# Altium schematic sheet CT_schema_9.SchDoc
size 274 x 160 mm
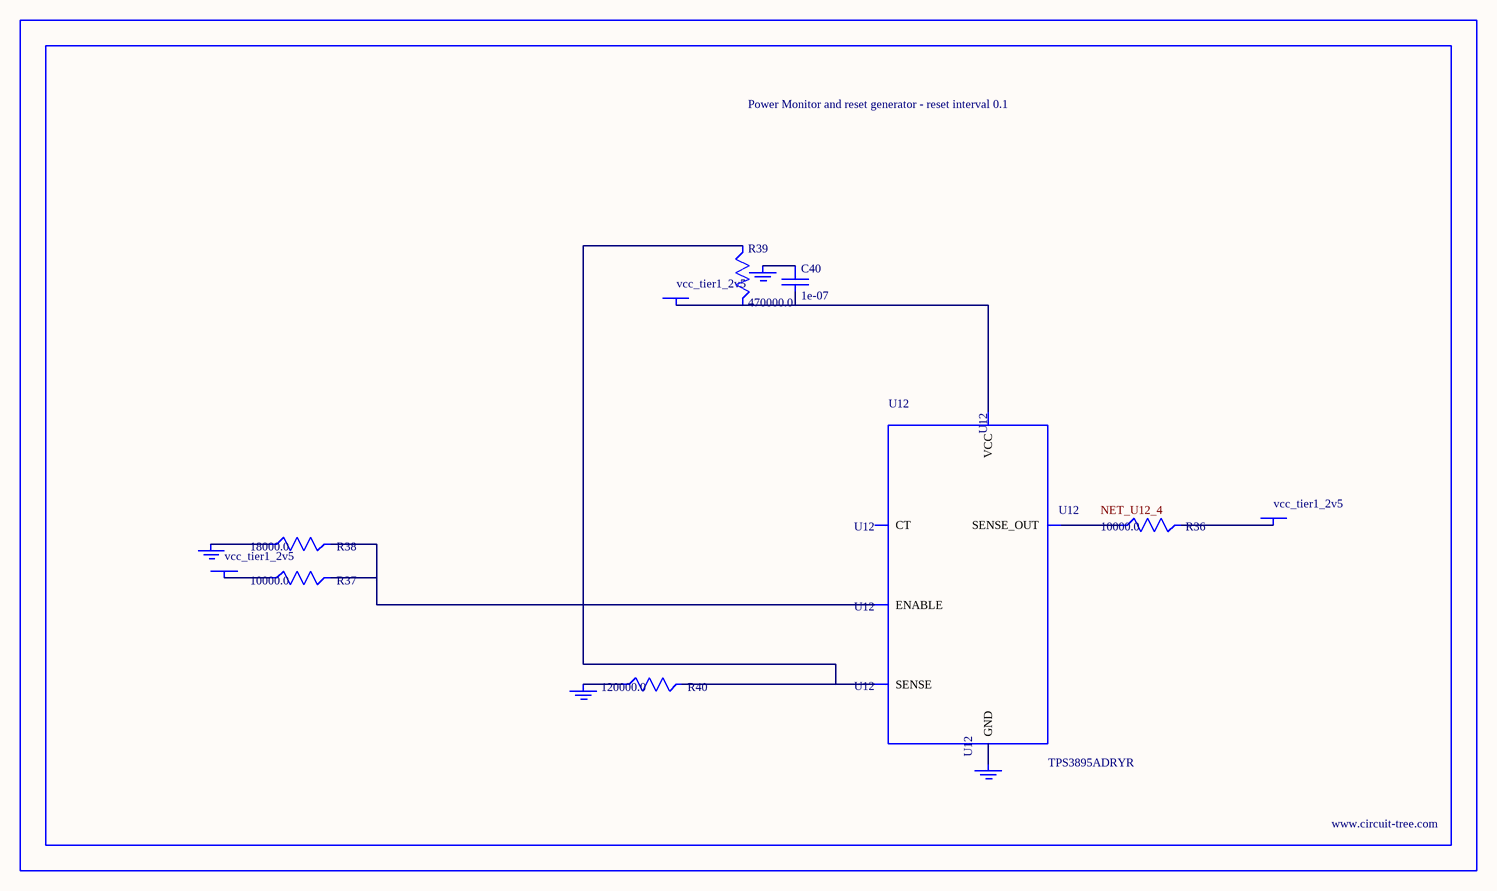
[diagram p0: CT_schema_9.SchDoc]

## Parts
BORDER8  (no value)
C40  1e-07  [C0402]
GND_INSTANCE_8_0  (no value)
GND_INSTANCE_8_1  (no value)
GND_INSTANCE_8_2  (no value)
GND_INSTANCE_8_3  (no value)
POWER_INSTANCE_8_0  vcc_tier1_2v5
POWER_INSTANCE_8_1  vcc_tier1_2v5
POWER_INSTANCE_8_2  vcc_tier1_2v5
R36  10000.0  [R0603]
R37  10000.0  [R0603]
R38  18000.0  [R0603]
R39  470000.0  [R0603]
R40  120000.0  [R0603]
U12  TPS3895ADRYR  [SON-6]

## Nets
NetC40_1: C40.1 GND_INSTANCE_8_2.0(GND)
NetC40_2: C40.2 POWER_INSTANCE_8_2.0(PWR) R39.2 U12.6(VCC)
NetGND_INSTANCE_8_0_0: GND_INSTANCE_8_0.0(GND) R38.1
NetGND_INSTANCE_8_1_0: GND_INSTANCE_8_1.0(GND) R40.1
NetGND_INSTANCE_8_3_0: GND_INSTANCE_8_3.0(GND) U12.2(GND)
NetPOWER_INSTANCE_8_0_0: POWER_INSTANCE_8_0.0(PWR) R37.1
NetPOWER_INSTANCE_8_1_0: POWER_INSTANCE_8_1.0(PWR) R36.2
NetR36_1: R36.1 U12.4(SENSE_OUT)
NetR37_2: R37.2 R38.2 U12.1(ENABLE)
NetR39_1: R39.1 R40.2 U12.3(SENSE)

Not connected (* = marked no-connect by the designer): U12 5(CT)

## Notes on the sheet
- Labels drawn without touching a wire or pin: NET_U12_4

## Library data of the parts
BORDER8 = BORDER_PAGE8
C40 = C0402C104K3RACTU
GND_INSTANCE_8_0-GND_INSTANCE_8_3 = GND
POWER_INSTANCE_8_0-POWER_INSTANCE_8_2 = PWR
R36 R37 = RC0603JR-0710KL
R38 = RC0603JR-0718KL
R39 = RC0603JR-07470KL
R40 = RC0603JR-07120KL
